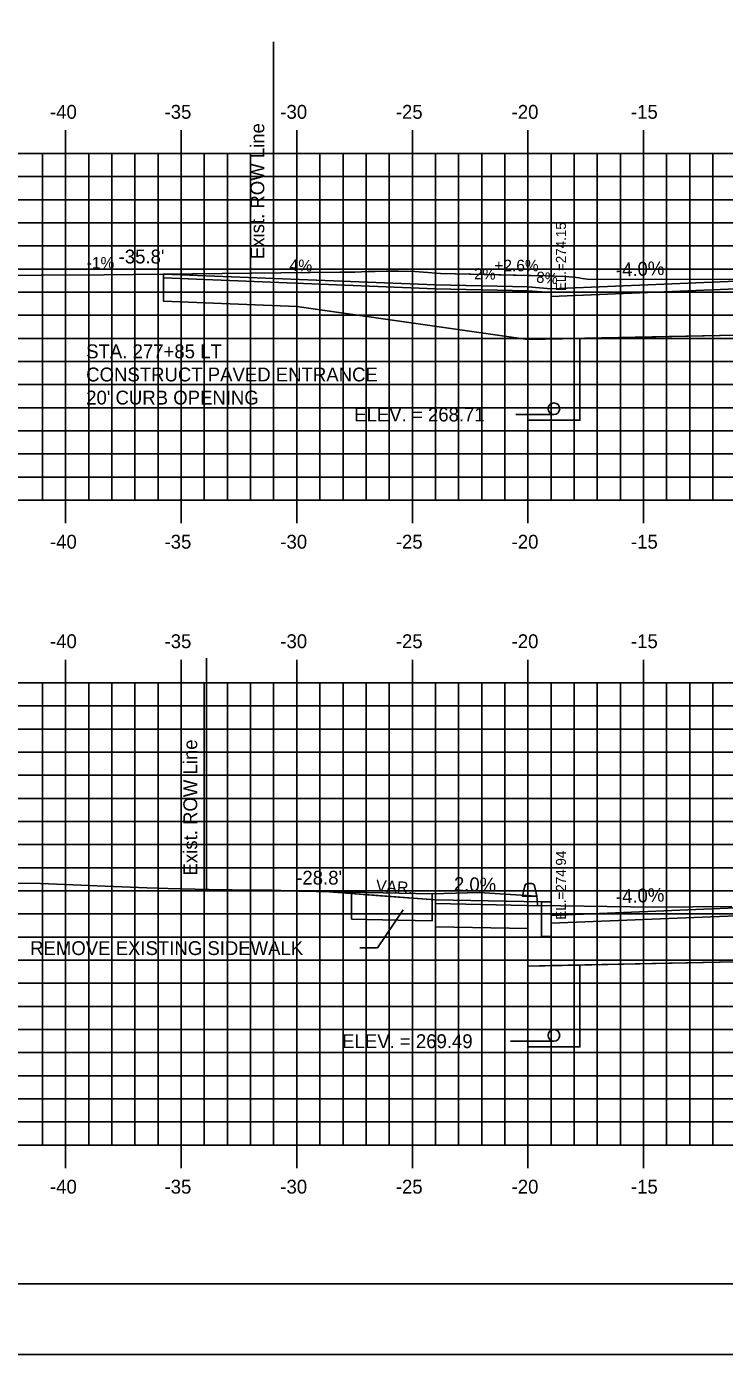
# Model space of a CAD drawing. Extents: x 854453 to 854623, y 366268 to 366378.
# Drawn here: x 854494.8 to 854524.9, y 366268.2 to 366325.6 of the extents above; entities that cross this region are included whole.
import ezdxf

# ---------------------------------------------------------------- set-up
doc = ezdxf.new("R2010")
doc.units = 0
for name, color, linetype in [('ANNOTATION', 7, 'Continuous'), ('BORDER', 7, 'Continuous'), ('D_Curb_Type_1_Lt', 7, 'Continuous'), ('D_Roadway_Drive_Gravel_LT', 7, 'Continuous'), ('D_Roadway_Drive_SubGrade', 7, 'Continuous'), ('D_Roadway_Edge_Shoulder', 7, 'Continuous'), ('D_Roadway_Edge_TW', 7, 'Continuous'), ('D_Roadway_FinishedGrade', 7, 'Continuous'), ('D_Roadway_Sidewalks_Paved', 7, 'Continuous'), ('D_Roadway_SubGrade', 7, 'Continuous'), ('D_Text_Standard', 7, 'Continuous'), ('E_ROW_Line', 7, 'Continuous'), ('H_V ANNOTATION', 7, 'Continuous'), ('JUNK COM EXC', 7, 'Continuous'), ('junk strct exc', 7, 'Continuous'), ('MAJOR', 7, 'Continuous'), ('MINOR', 7, 'Continuous'), ('PDRAIN', 7, 'Continuous'), ('PLOT BOUNDARY', 7, 'Continuous'), ('S_Curb_Type_3', 7, 'Continuous'), ('S_Roadway_Centerline', 7, 'Continuous'), ('TEXT', 7, 'Continuous')]:
    doc.layers.add(name, color=color, linetype=linetype)

msp = doc.modelspace()

# ---------------------------------------------------------------- linework, layer by layer
at = {"layer": 'ANNOTATION'}
msp.add_lwpolyline([(854509.173, 366285.775), (854509.926, 366285.775), (854511.041, 366287.408)], dxfattribs=at)
at = {"layer": 'BORDER'}
msp.add_line((854461.439, 366271.236), (854621.439, 366271.236), dxfattribs=at)
at = {"layer": 'D_Curb_Type_1_Lt'}
msp.add_lwpolyline([(854517.022, 366287.758), (854517.022, 366286.258), (854517.439, 366286.258), (854517.439, 366287.758)], close=True, dxfattribs=at)
at = {"layer": 'D_Roadway_Drive_Gravel_LT'}
for p, q in [((854512.439, 366314.45), (854500.671, 366314.92)), ((854512.434, 366314.283), (854500.671, 366314.753)), ((854516.439, 366314.37), (854512.439, 366314.45)), ((854512.439, 366314.45), (854512.439, 366314.45)), ((854517.439, 366314.29), (854516.439, 366314.37)), ((854516.43, 366314.203), (854512.434, 366314.283)), ((854517.439, 366314.122), (854516.43, 366314.203)), ((854506.439, 366313.522), (854500.671, 366313.753))]:
    msp.add_line(p, q, dxfattribs=at)
at = {"layer": 'D_Roadway_Drive_SubGrade'}
for p, q in [((854500.671, 366314.92), (854500.671, 366313.754)), ((854516.439, 366312.096), (854506.439, 366313.522)), ((854517.439, 366312.116), (854516.439, 366312.096))]:
    msp.add_line(p, q, dxfattribs=at)
at = {"layer": 'D_Roadway_Edge_Shoulder'}
msp.add_lwpolyline([(854517.439, 366314.29), (854525.439, 366314.61), (854536.439, 366314.467), (854547.439, 366314.247), (854555.434, 366313.927)], dxfattribs=at)
at = {"layer": 'D_Roadway_Edge_TW'}
msp.add_lwpolyline([(854517.439, 366287.174), (854525.439, 366287.494), (854547.439, 366287.054), (854555.434, 366286.734)], dxfattribs=at)
at = {"layer": 'D_Roadway_FinishedGrade'}
msp.add_line((854512.434, 366287.85), (854507.664, 366288.204), dxfattribs=at)
at = {"layer": 'D_Roadway_Sidewalks_Paved'}
msp.add_lwpolyline([(854512.434, 366287.85), (854517.022, 366287.758), (854517.022, 366287.591), (854512.434, 366287.683)], close=True, dxfattribs=at)
at = {"layer": 'D_Roadway_SubGrade'}
for points in [[(854525.439, 366314.276), (854517.439, 366313.956), (854517.439, 366312.116), (854525.439, 366312.276)], [(854525.439, 366287.161), (854517.439, 366286.841), (854517.439, 366285.001), (854525.439, 366285.161)]]:
    msp.add_lwpolyline(points, close=True, dxfattribs=at)
msp.add_lwpolyline([(854512.434, 366287.683), (854512.434, 366286.683), (854516.439, 366286.603), (854516.439, 366284.981), (854517.439, 366285.001)], dxfattribs=at)
at = {"layer": 'D_Text_Standard'}
for points in [[(854517.564, 366308.846), (854516.597, 366308.846), (854515.917, 366308.846)], [(854517.564, 366281.731), (854516.365, 366281.731), (854515.685, 366281.731)]]:
    msp.add_lwpolyline(points, dxfattribs=at)
at = {"layer": 'E_ROW_Line'}
for p, q in [((854505.435, 366314.969), (854505.435, 366324.969)), ((854502.532, 366288.301), (854502.532, 366298.301))]:
    msp.add_line(p, q, dxfattribs=at)
at = {"layer": 'JUNK COM EXC'}
for points in [[(854516.439, 366314.863), (854512.651, 366314.94), (854511.915, 366315.006), (854511.544, 366315.03), (854510.846, 366315.052), (854510.302, 366315.049), (854509.833, 366315.038), (854509.524, 366315.029), (854508.956, 366315.01), (854508.71, 366315.004), (854508.298, 366315), (854500.671, 366314.92), (854500.671, 366313.753), (854506.439, 366313.522), (854516.439, 366312.096), (854516.439, 366314.863)], [(854525.794, 366314.691), (854518.996, 366314.706), (854518.789, 366314.735), (854518.654, 366314.752), (854518.406, 366314.781), (854518.022, 366314.822), (854517.232, 366314.847), (854516.439, 366314.863), (854516.439, 366312.096), (854525.439, 366312.276)], [(854525.262, 366287.564), (854521.88, 366287.531), (854516.856, 366287.6), (854516.837, 366287.858), (854516.822, 366288.01), (854514.333, 366288.163), (854512.289, 366288.102), (854510.856, 366288.135), (854508.805, 366288.181), (854507.664, 366288.204), (854510.049, 366288.027), (854512.434, 366287.85), (854512.434, 366286.683), (854516.439, 366286.603), (854516.439, 366284.981), (854525.439, 366285.161)]]:
    msp.add_lwpolyline(points, dxfattribs=at)
at = {"layer": 'junk strct exc'}
for points in [[(854516.439, 366312.096), (854516.439, 366308.596), (854518.689, 366308.596), (854518.689, 366312.141)], [(854516.439, 366284.981), (854516.439, 366281.481), (854518.689, 366281.481), (854518.689, 366285.026)]]:
    msp.add_lwpolyline(points, close=True, dxfattribs=at)
at = {"layer": 'MAJOR'}
for p, q in [((854496.439, 366321.143), (854496.439, 366320.141)), ((854501.439, 366321.143), (854501.439, 366320.141)), ((854506.439, 366321.143), (854506.439, 366320.141)), ((854511.439, 366321.143), (854511.439, 366320.141)), ((854516.439, 366321.143), (854516.439, 366320.141)), ((854521.439, 366321.143), (854521.439, 366320.141)), ((854466.439, 366320.141), (854606.439, 366320.141)), ((854466.439, 366320.141), (854606.439, 366320.141)), ((854496.439, 366305.141), (854496.439, 366320.141)), ((854501.439, 366305.141), (854501.439, 366320.141)), ((854506.439, 366305.141), (854506.439, 366320.141)), ((854511.439, 366305.141), (854511.439, 366320.141)), ((854516.439, 366305.141), (854516.439, 366320.141)), ((854521.439, 366305.141), (854521.439, 366320.141)), ((854466.439, 366315.141), (854606.439, 366315.141)), ((854466.439, 366310.141), (854606.439, 366310.141)), ((854466.439, 366305.141), (854606.439, 366305.141)), ((854466.439, 366305.141), (854606.439, 366305.141)), ((854496.439, 366304.139), (854496.439, 366305.141)), ((854501.439, 366304.139), (854501.439, 366305.141)), ((854506.439, 366304.139), (854506.439, 366305.141)), ((854511.439, 366304.139), (854511.439, 366305.141)), ((854516.439, 366304.139), (854516.439, 366305.141)), ((854521.439, 366304.139), (854521.439, 366305.141)), ((854496.439, 366298.238), (854496.439, 366297.236)), ((854501.439, 366298.238), (854501.439, 366297.236)), ((854506.439, 366298.238), (854506.439, 366297.236)), ((854511.439, 366298.238), (854511.439, 366297.236)), ((854516.439, 366298.238), (854516.439, 366297.236)), ((854521.439, 366298.238), (854521.439, 366297.236)), ((854466.439, 366297.236), (854606.439, 366297.236)), ((854466.439, 366297.236), (854606.439, 366297.236)), ((854496.439, 366277.236), (854496.439, 366297.236)), ((854501.439, 366277.236), (854501.439, 366297.236)), ((854506.439, 366277.236), (854506.439, 366297.236)), ((854511.439, 366277.236), (854511.439, 366297.236)), ((854516.439, 366277.236), (854516.439, 366297.236)), ((854521.439, 366277.236), (854521.439, 366297.236)), ((854466.439, 366292.236), (854606.439, 366292.236)), ((854466.439, 366287.236), (854606.439, 366287.236)), ((854466.439, 366282.236), (854606.439, 366282.236)), ((854466.439, 366277.236), (854606.439, 366277.236)), ((854466.439, 366277.236), (854606.439, 366277.236)), ((854496.439, 366276.234), (854496.439, 366277.236)), ((854501.439, 366276.234), (854501.439, 366277.236)), ((854506.439, 366276.234), (854506.439, 366277.236)), ((854511.439, 366276.234), (854511.439, 366277.236)), ((854516.439, 366276.234), (854516.439, 366277.236)), ((854521.439, 366276.234), (854521.439, 366277.236))]:
    msp.add_line(p, q, dxfattribs=at)
at = {"layer": 'MINOR'}
for p, q in [((854495.439, 366305.141), (854495.439, 366320.141)), ((854497.439, 366305.141), (854497.439, 366320.141)), ((854498.439, 366305.141), (854498.439, 366320.141)), ((854499.439, 366305.141), (854499.439, 366320.141)), ((854500.439, 366305.141), (854500.439, 366320.141)), ((854502.439, 366305.141), (854502.439, 366320.141)), ((854503.439, 366305.141), (854503.439, 366320.141)), ((854504.439, 366305.141), (854504.439, 366320.141)), ((854505.439, 366305.141), (854505.439, 366320.141)), ((854507.439, 366305.141), (854507.439, 366320.141)), ((854508.439, 366305.141), (854508.439, 366320.141)), ((854509.439, 366305.141), (854509.439, 366320.141)), ((854510.439, 366305.141), (854510.439, 366320.141)), ((854512.439, 366305.141), (854512.439, 366320.141)), ((854513.439, 366305.141), (854513.439, 366320.141)), ((854514.439, 366305.141), (854514.439, 366320.141)), ((854515.439, 366305.141), (854515.439, 366320.141)), ((854517.439, 366305.141), (854517.439, 366320.141)), ((854518.439, 366305.141), (854518.439, 366320.141)), ((854519.439, 366305.141), (854519.439, 366320.141)), ((854520.439, 366305.141), (854520.439, 366320.141)), ((854522.439, 366305.141), (854522.439, 366320.141)), ((854523.439, 366305.141), (854523.439, 366320.141)), ((854524.439, 366305.141), (854524.439, 366320.141)), ((854466.439, 366319.141), (854606.439, 366319.141)), ((854466.439, 366318.141), (854606.439, 366318.141)), ((854466.439, 366317.141), (854606.439, 366317.141)), ((854466.439, 366316.141), (854606.439, 366316.141)), ((854466.439, 366314.141), (854606.439, 366314.141)), ((854466.439, 366313.141), (854606.439, 366313.141)), ((854466.439, 366312.141), (854606.439, 366312.141)), ((854466.439, 366311.141), (854606.439, 366311.141)), ((854466.439, 366309.141), (854606.439, 366309.141)), ((854466.439, 366308.141), (854606.439, 366308.141)), ((854466.439, 366307.141), (854606.439, 366307.141)), ((854466.439, 366306.141), (854606.439, 366306.141)), ((854495.439, 366277.236), (854495.439, 366297.236)), ((854497.439, 366277.236), (854497.439, 366297.236)), ((854498.439, 366277.236), (854498.439, 366297.236)), ((854499.439, 366277.236), (854499.439, 366297.236)), ((854500.439, 366277.236), (854500.439, 366297.236)), ((854502.439, 366277.236), (854502.439, 366297.236)), ((854503.439, 366277.236), (854503.439, 366297.236)), ((854504.439, 366277.236), (854504.439, 366297.236)), ((854505.439, 366277.236), (854505.439, 366297.236)), ((854507.439, 366277.236), (854507.439, 366297.236)), ((854508.439, 366277.236), (854508.439, 366297.236)), ((854509.439, 366277.236), (854509.439, 366297.236)), ((854510.439, 366277.236), (854510.439, 366297.236)), ((854512.439, 366277.236), (854512.439, 366297.236)), ((854513.439, 366277.236), (854513.439, 366297.236)), ((854514.439, 366277.236), (854514.439, 366297.236)), ((854515.439, 366277.236), (854515.439, 366297.236)), ((854517.439, 366277.236), (854517.439, 366297.236)), ((854518.439, 366277.236), (854518.439, 366297.236)), ((854519.439, 366277.236), (854519.439, 366297.236)), ((854520.439, 366277.236), (854520.439, 366297.236)), ((854522.439, 366277.236), (854522.439, 366297.236)), ((854523.439, 366277.236), (854523.439, 366297.236)), ((854524.439, 366277.236), (854524.439, 366297.236)), ((854466.439, 366296.236), (854606.439, 366296.236)), ((854466.439, 366295.236), (854606.439, 366295.236)), ((854466.439, 366294.236), (854606.439, 366294.236)), ((854466.439, 366293.236), (854606.439, 366293.236)), ((854466.439, 366291.236), (854606.439, 366291.236)), ((854466.439, 366290.236), (854606.439, 366290.236)), ((854466.439, 366289.236), (854606.439, 366289.236)), ((854466.439, 366288.236), (854606.439, 366288.236)), ((854466.439, 366286.236), (854606.439, 366286.236)), ((854466.439, 366285.236), (854606.439, 366285.236)), ((854466.439, 366284.236), (854606.439, 366284.236)), ((854466.439, 366283.236), (854606.439, 366283.236)), ((854466.439, 366281.236), (854606.439, 366281.236)), ((854466.439, 366280.236), (854606.439, 366280.236)), ((854466.439, 366279.236), (854606.439, 366279.236)), ((854466.439, 366278.236), (854606.439, 366278.236))]:
    msp.add_line(p, q, dxfattribs=at)
at = {"layer": 'PDRAIN'}
for points in [[(854516.439, 366312.096), (854516.439, 366308.596), (854518.689, 366308.596), (854518.689, 366312.096)], [(854516.439, 366284.981), (854516.439, 366281.481), (854518.689, 366281.481), (854518.689, 366284.981)]]:
    msp.add_lwpolyline(points, dxfattribs=at)
for centre in [(854517.564, 366309.096), (854517.564, 366281.981)]:
    msp.add_circle(centre, 0.25, dxfattribs=at)
at = {"layer": 'PLOT BOUNDARY'}
msp.add_lwpolyline([(854453.345, 366268.177), (854623.345, 366268.177), (854623.345, 366378.177), (854453.345, 366378.177)], close=True, dxfattribs=at)
at = {"layer": 'S_Curb_Type_3'}
for points in [[(854516.598, 366288.552), (854516.422, 366288.552)], [(854516.3, 366288.455), (854516.197, 366288.01), (854516.822, 366288.01), (854516.72, 366288.455)]]:
    msp.add_lwpolyline(points, dxfattribs=at)
for centre, start, end in [((854516.422, 366288.427), 90, 167.00538), ((854516.598, 366288.427), 12.99462, 90)]:
    msp.add_arc(centre, 0.125, start, end, dxfattribs=at)
at = {"layer": 'S_Roadway_Centerline'}
for p, q in [((854508.805, 366287.014), (854508.805, 366288.181)), ((854512.289, 366286.935), (854512.289, 366288.102))]:
    msp.add_line(p, q, dxfattribs=at)
for points in [[(854487.191, 366314.837), (854498.101, 366314.894), (854508.298, 366315), (854508.71, 366315.004), (854508.956, 366315.01), (854509.524, 366315.029), (854509.833, 366315.038), (854510.302, 366315.049), (854510.846, 366315.052), (854511.544, 366315.03), (854511.915, 366315.006), (854512.651, 366314.94), (854517.232, 366314.847), (854518.022, 366314.822), (854518.406, 366314.781), (854518.654, 366314.752), (854518.789, 366314.735), (854518.996, 366314.706), (854525.794, 366314.691)], [(854493.517, 366288.569), (854495.355, 366288.554), (854497.785, 366288.448), (854499.958, 366288.363), (854500.858, 366288.335), (854502.631, 366288.299), (854503.639, 366288.286), (854505.361, 366288.26), (854506.524, 366288.227), (854508.805, 366288.181), (854510.856, 366288.135), (854512.289, 366288.102), (854514.333, 366288.163), (854516.822, 366288.01), (854516.837, 366287.858), (854516.856, 366287.6), (854521.88, 366287.531), (854525.262, 366287.564)], [(854508.805, 366287.014), (854510.829, 366286.968), (854512.289, 366286.935)]]:
    msp.add_lwpolyline(points, dxfattribs=at)

# ---------------------------------------------------------------- texts
at = {"layer": 'ANNOTATION'}
for s, rotation, p in [('-4.0%', 2.29061, (854520.255, 366314.803)), ('2.0%', 358.85424, (854513.231, 366288.234)), ('-4.0%', 2.29061, (854520.255, 366287.688))]:
    msp.add_text(s, height=0.6, rotation=rotation, dxfattribs=at).set_placement(p)
for s, p in [('STA. 277+85 LT', (854497.33, 366311.277)), ('CONSTRUCT PAVED ENTRANCE', (854497.33, 366310.277)), ("20' CURB OPENING", (854497.33, 366309.277)), ('REMOVE EXISTING SIDEWALK', (854494.904, 366285.458))]:
    msp.add_text(s, height=0.6, dxfattribs=at).set_placement(p)
at = {"layer": 'D_Roadway_Drive_Gravel_LT'}
for s, height, rotation, p in [('4%', 0.51, 357.70939, (854506.114, 366315.06)), ('2%', 0.48, 358.80778, (854514.109, 366314.698)), ('8%', 0.48, 355.42608, (854516.784, 366314.557))]:
    msp.add_text(s, height=height, rotation=rotation, dxfattribs=at).set_placement(p)
at = {"layer": 'D_Text_Standard'}
for s, height, rotation, p in [(' EL.=274.15', 0.4335, 90, (854518.082, 366314.021)), (' EL.=274.94', 0.4335, 90, (854518.082, 366286.829)), ('VAR.', 0.51, 356.08069, (854509.85, 366288.21))]:
    msp.add_text(s, height=height, rotation=rotation, dxfattribs=at).set_placement(p)
for s, p in [("-35.8'", (854498.733, 366315.38)), ('ELEV. = 268.71', (854508.924, 366308.546)), ("-28.8'", (854506.415, 366288.505)), ('ELEV. = 269.49', (854508.403, 366281.431))]:
    msp.add_text(s, height=0.6, dxfattribs=at).set_placement(p)
at = {"layer": 'E_ROW_Line'}
for p in [(854505.035, 366315.569), (854502.132, 366288.901)]:
    msp.add_text('Exist. ROW Line', height=0.6, rotation=90, dxfattribs=at).set_placement(p)
at = {"layer": 'H_V ANNOTATION'}
for s, p in [('-40', (854495.764, 366321.641)), ('-35', (854500.719, 366321.641)), ('-30', (854505.727, 366321.641)), ('-25', (854510.724, 366321.641)), ('-20', (854515.732, 366321.641)), ('-15', (854520.895, 366321.641)), ('-40', (854495.764, 366303.041)), ('-35', (854500.719, 366303.041)), ('-30', (854505.727, 366303.041)), ('-25', (854510.724, 366303.041)), ('-20', (854515.732, 366303.041)), ('-15', (854520.895, 366303.041)), ('-40', (854495.764, 366298.736)), ('-35', (854500.719, 366298.736)), ('-30', (854505.727, 366298.736)), ('-25', (854510.724, 366298.736)), ('-20', (854515.732, 366298.736)), ('-15', (854520.895, 366298.736)), ('-40', (854495.764, 366275.136)), ('-35', (854500.719, 366275.136)), ('-30', (854505.727, 366275.136)), ('-25', (854510.724, 366275.136)), ('-20', (854515.732, 366275.136)), ('-15', (854520.895, 366275.136))]:
    msp.add_text(s, height=0.6, dxfattribs=at).set_placement(p)
at = {"layer": 'TEXT'}
for s, p in [('-1%', (854497.356, 366315.158)), ('+2.6%', (854514.988, 366315.042))]:
    msp.add_text(s, height=0.5, dxfattribs=at).set_placement(p)

doc.saveas('drawing.dxf')
